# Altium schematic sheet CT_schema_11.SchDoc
size 274 x 160 mm
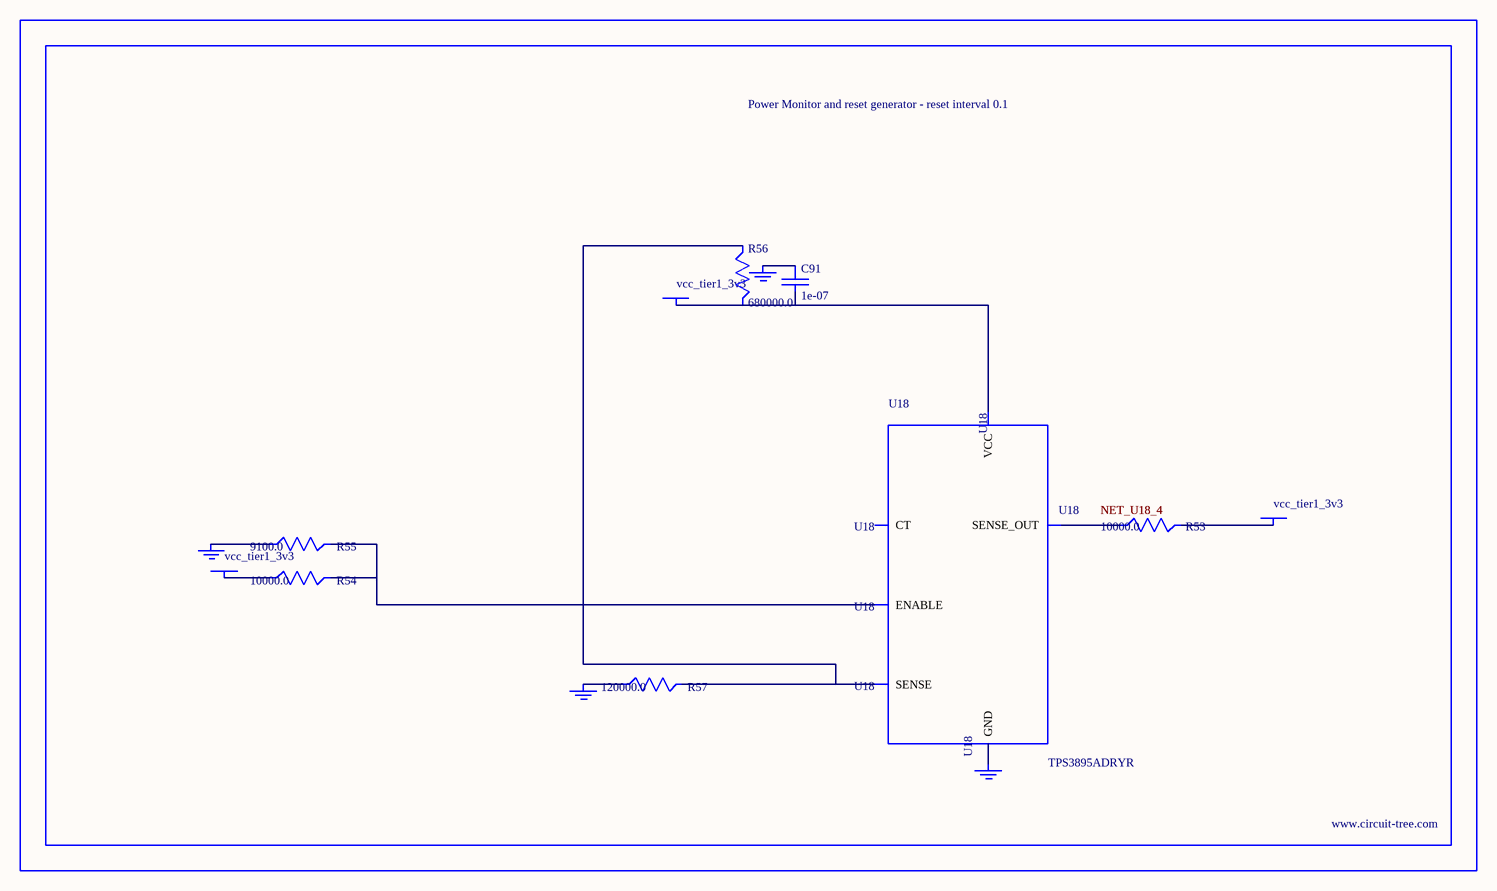
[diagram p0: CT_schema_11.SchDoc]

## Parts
BORDER10  (no value)
C91  1e-07  [C0402]
GND_INSTANCE_10_0  (no value)
GND_INSTANCE_10_1  (no value)
GND_INSTANCE_10_2  (no value)
GND_INSTANCE_10_3  (no value)
POWER_INSTANCE_10_0  vcc_tier1_3v3
POWER_INSTANCE_10_1  vcc_tier1_3v3
POWER_INSTANCE_10_2  vcc_tier1_3v3
R53  10000.0  [R0603]
R54  10000.0  [R0603]
R55  9100.0  [R0603]
R56  680000.0  [R0603]
R57  120000.0  [R0603]
U18  TPS3895ADRYR  [SON-6]

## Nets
NetC91_1: C91.1 GND_INSTANCE_10_2.0(GND)
NetC91_2: C91.2 POWER_INSTANCE_10_2.0(PWR) R56.2 U18.6(VCC)
NetGND_INSTANCE_10_0_0: GND_INSTANCE_10_0.0(GND) R55.1
NetGND_INSTANCE_10_1_0: GND_INSTANCE_10_1.0(GND) R57.1
NetGND_INSTANCE_10_3_0: GND_INSTANCE_10_3.0(GND) U18.2(GND)
NetPOWER_INSTANCE_10_0_0: POWER_INSTANCE_10_0.0(PWR) R54.1
NetPOWER_INSTANCE_10_1_0: POWER_INSTANCE_10_1.0(PWR) R53.2
NetR53_1: R53.1 U18.4(SENSE_OUT)
NetR54_2: R54.2 R55.2 U18.1(ENABLE)
NetR56_1: R56.1 R57.2 U18.3(SENSE)

Not connected (* = marked no-connect by the designer): U18 5(CT)

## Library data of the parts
BORDER10 = BORDER_PAGE10
C91 = C0402C104K3RACTU
GND_INSTANCE_10_0-GND_INSTANCE_10_3 = GND
POWER_INSTANCE_10_0-POWER_INSTANCE_10_2 = PWR
R53 R54 = RC0603JR-0710KL
R55 = RC0603JR-079K1L
R56 = RC0603JR-07680KL
R57 = RC0603JR-07120KL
